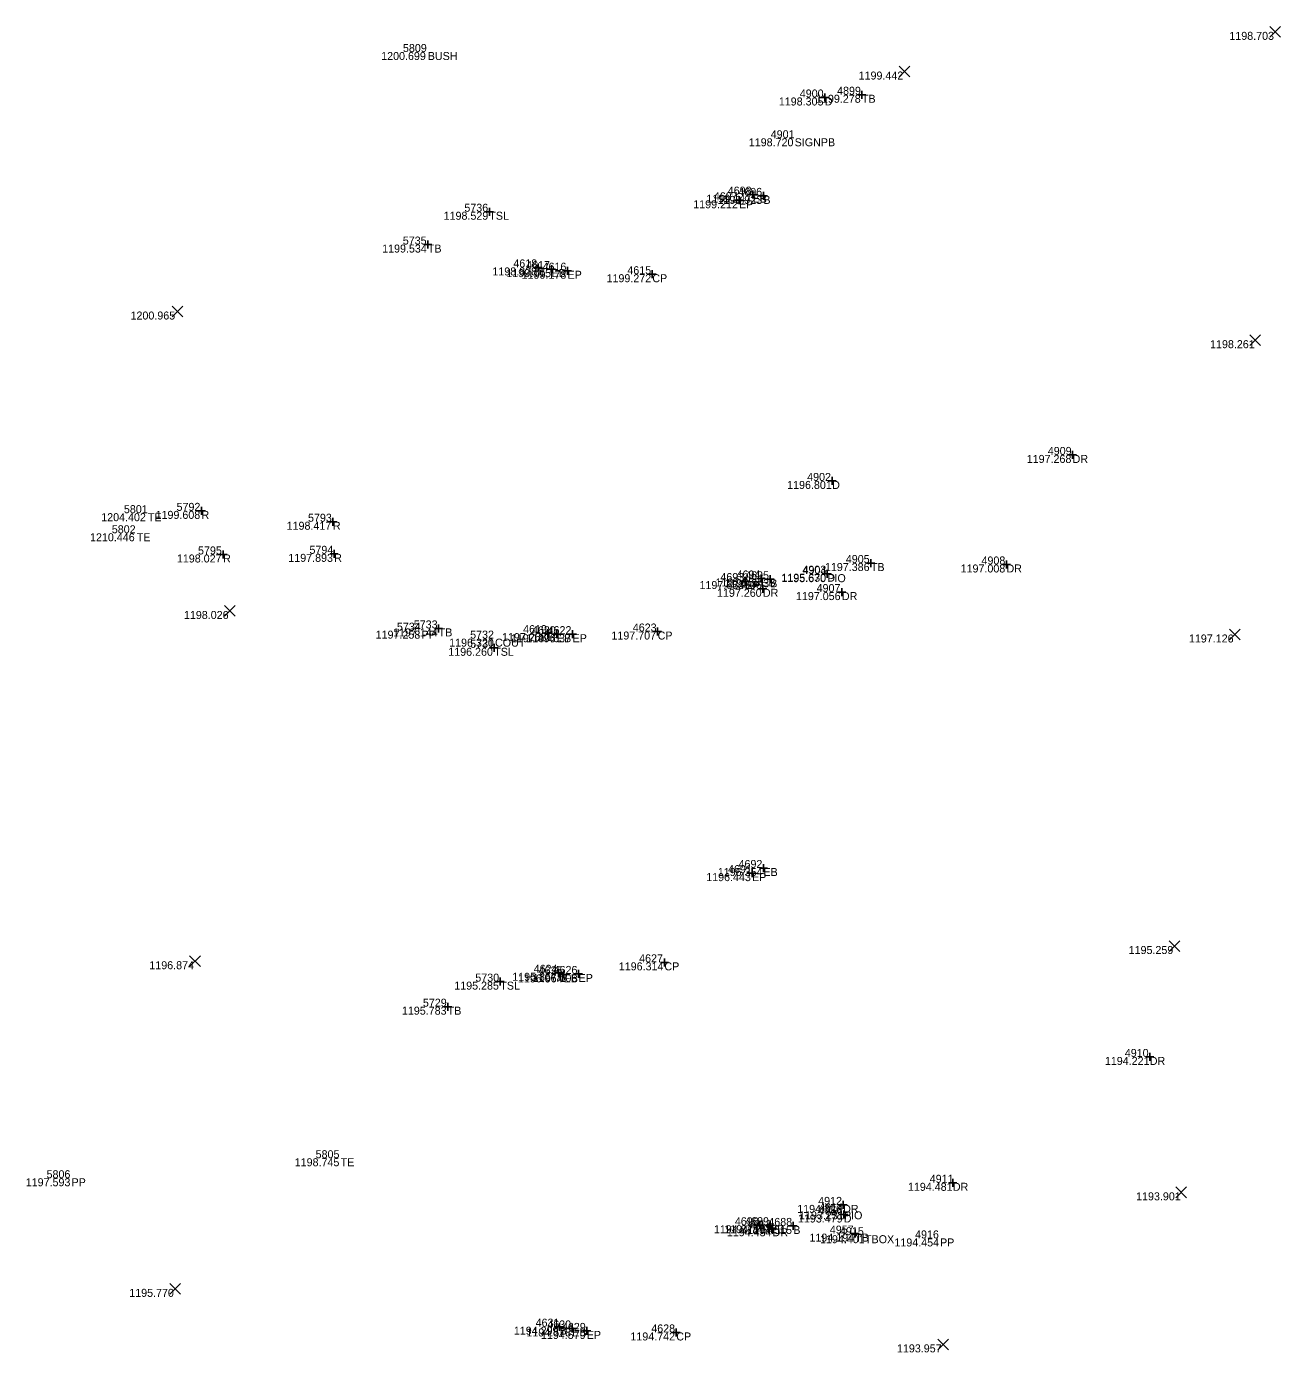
# Model space of a CAD drawing. Extents: x 2044997 to 2050342, y 455233 to 458054.
# Drawn here: x 2047566.8 to 2047723.4, y 456309.9 to 456475.6 of the extents above; entities that cross this region are included whole.
import ezdxf

# ---------------------------------------------------------------- set-up
doc = ezdxf.new("R2010")
doc.units = 0
for name, color, linetype in [('SV_X_Random_Point', 7, 'Continuous'), ('SV_X_Shot_Marker', 7, 'Continuous'), ('SV_X_Text_Comment', 7, 'Continuous'), ('SV_X_Text_Elevation', 7, 'Continuous'), ('SV_X_Text_Name', 7, 'Continuous')]:
    doc.layers.add(name, color=color, linetype=linetype)

msp = doc.modelspace()

# ---------------------------------------------------------------- linework, layer by layer
at = {"layer": 'SV_X_Random_Point'}
for p, q in [((2047722.08, 456474.27), (2047723.42, 456475.61)), ((2047722.08, 456475.61), (2047723.42, 456474.27)), ((2047675.78, 456469.31), (2047677.11, 456470.64)), ((2047675.78, 456470.64), (2047677.11, 456469.31)), ((2047584.95, 456439.32), (2047586.29, 456440.66)), ((2047584.95, 456440.66), (2047586.29, 456439.32)), ((2047719.57, 456435.74), (2047720.9, 456437.07)), ((2047719.57, 456437.07), (2047720.9, 456435.74)), ((2047591.51, 456401.9), (2047592.84, 456403.24)), ((2047591.51, 456403.24), (2047592.84, 456401.9)), ((2047717.05, 456398.97), (2047718.39, 456400.3)), ((2047717.05, 456400.3), (2047718.39, 456398.97)), ((2047709.5, 456360.03), (2047710.83, 456361.36)), ((2047709.5, 456361.36), (2047710.83, 456360.03)), ((2047587.15, 456358.13), (2047588.49, 456359.46)), ((2047587.15, 456359.46), (2047588.49, 456358.13)), ((2047710.33, 456329.25), (2047711.66, 456330.59)), ((2047710.33, 456330.59), (2047711.66, 456329.25)), ((2047584.67, 456317.19), (2047586.01, 456318.53)), ((2047584.67, 456318.53), (2047586.01, 456317.19)), ((2047680.62, 456310.25), (2047681.95, 456311.59)), ((2047680.62, 456311.59), (2047681.95, 456310.25))]:
    msp.add_line(p, q, dxfattribs=at)
at = {"layer": 'SV_X_Shot_Marker'}
for p, q in [((2047665.99, 456466.74), (2047666.99, 456466.74)), ((2047666.49, 456467.24), (2047666.49, 456466.24)), ((2047666.49, 456466.74), (2047666.49, 456466.74)), ((2047670.63, 456467.08), (2047671.63, 456467.08)), ((2047671.13, 456467.58), (2047671.13, 456466.58)), ((2047671.13, 456467.08), (2047671.13, 456467.08)), ((2047657.49, 456455.1), (2047657.49, 456454.1)), ((2047658.82, 456454.94), (2047658.82, 456453.94)), ((2047655.29, 456453.89), (2047656.29, 456453.89)), ((2047655.79, 456454.39), (2047655.79, 456453.39)), ((2047655.79, 456453.89), (2047655.79, 456453.89)), ((2047656.99, 456454.6), (2047657.99, 456454.6)), ((2047657.49, 456454.6), (2047657.49, 456454.6)), ((2047658.32, 456454.44), (2047659.32, 456454.44)), ((2047658.82, 456454.44), (2047658.82, 456454.44)), ((2047624.09, 456452.46), (2047625.09, 456452.46)), ((2047624.59, 456452.96), (2047624.59, 456451.96)), ((2047624.59, 456452.46), (2047624.59, 456452.46)), ((2047616.41, 456448.36), (2047617.41, 456448.36)), ((2047616.91, 456448.86), (2047616.91, 456447.86)), ((2047616.91, 456448.36), (2047616.91, 456448.36)), ((2047630.21, 456445.5), (2047631.21, 456445.5)), ((2047630.71, 456446), (2047630.71, 456445)), ((2047630.71, 456445.5), (2047630.71, 456445.5)), ((2047631.86, 456445.29), (2047632.86, 456445.29)), ((2047632.36, 456445.79), (2047632.36, 456444.79)), ((2047632.36, 456445.29), (2047632.36, 456445.29)), ((2047633.86, 456445.09), (2047634.86, 456445.09)), ((2047634.36, 456445.59), (2047634.36, 456444.59)), ((2047634.36, 456445.09), (2047634.36, 456445.09)), ((2047644.95, 456445.15), (2047644.95, 456444.15)), ((2047644.45, 456444.65), (2047645.45, 456444.65)), ((2047644.95, 456444.65), (2047644.95, 456444.65)), ((2047696.95, 456422.07), (2047697.95, 456422.07)), ((2047697.45, 456422.57), (2047697.45, 456421.57)), ((2047697.45, 456422.07), (2047697.45, 456422.07)), ((2047666.91, 456418.82), (2047667.91, 456418.82)), ((2047667.41, 456419.32), (2047667.41, 456418.32)), ((2047667.41, 456418.82), (2047667.41, 456418.82)), ((2047588.13, 456415.08), (2047589.13, 456415.08)), ((2047588.63, 456415.58), (2047588.63, 456414.58)), ((2047588.63, 456415.08), (2047588.63, 456415.08)), ((2047604.55, 456413.72), (2047605.55, 456413.72)), ((2047605.05, 456414.22), (2047605.05, 456413.22)), ((2047605.05, 456413.72), (2047605.05, 456413.72)), ((2047591.33, 456410.13), (2047591.33, 456409.13)), ((2047605.21, 456410.21), (2047605.21, 456409.21)), ((2047590.83, 456409.63), (2047591.83, 456409.63)), ((2047591.33, 456409.63), (2047591.33, 456409.63)), ((2047604.71, 456409.71), (2047605.71, 456409.71)), ((2047605.21, 456409.71), (2047605.21, 456409.71)), ((2047671.75, 456408.56), (2047672.75, 456408.56)), ((2047672.25, 456409.06), (2047672.25, 456408.06)), ((2047672.25, 456408.56), (2047672.25, 456408.56)), ((2047688.69, 456408.38), (2047689.69, 456408.38)), ((2047689.19, 456408.88), (2047689.19, 456407.88)), ((2047689.19, 456408.38), (2047689.19, 456408.38)), ((2047656.56, 456406.81), (2047656.56, 456405.81)), ((2047658.56, 456407.13), (2047658.56, 456406.13)), ((2047659.68, 456407.03), (2047659.68, 456406.03)), ((2047666.31, 456407.23), (2047667.31, 456407.23)), ((2047666.81, 456407.73), (2047666.81, 456406.73)), ((2047666.81, 456407.23), (2047666.81, 456407.23)), ((2047656.06, 456406.31), (2047657.06, 456406.31)), ((2047656.56, 456406.31), (2047656.56, 456406.31)), ((2047658.06, 456406.63), (2047659.06, 456406.63)), ((2047658.26, 456405.34), (2047659.26, 456405.34)), ((2047658.56, 456406.63), (2047658.56, 456406.63)), ((2047658.76, 456405.84), (2047658.76, 456404.84)), ((2047658.76, 456405.34), (2047658.76, 456405.34)), ((2047659.18, 456406.53), (2047660.18, 456406.53)), ((2047659.68, 456406.53), (2047659.68, 456406.53)), ((2047668.63, 456405.43), (2047668.63, 456404.43)), ((2047668.13, 456404.93), (2047669.13, 456404.93)), ((2047668.63, 456404.93), (2047668.63, 456404.93)), ((2047617.76, 456400.39), (2047618.76, 456400.39)), ((2047618.26, 456400.89), (2047618.26, 456399.89)), ((2047618.26, 456400.39), (2047618.26, 456400.39)), ((2047631.91, 456400.3), (2047631.91, 456399.3)), ((2047633.03, 456400.16), (2047633.03, 456399.16)), ((2047634.99, 456400.17), (2047634.99, 456399.17)), ((2047645.61, 456400.5), (2047645.61, 456399.5)), ((2047625.2, 456398.47), (2047625.2, 456397.47)), ((2047631.41, 456399.8), (2047632.41, 456399.8)), ((2047631.91, 456399.8), (2047631.91, 456399.8)), ((2047632.53, 456399.66), (2047633.53, 456399.66)), ((2047633.03, 456399.66), (2047633.03, 456399.66)), ((2047634.49, 456399.67), (2047635.49, 456399.67)), ((2047634.99, 456399.67), (2047634.99, 456399.67)), ((2047645.11, 456400), (2047646.11, 456400)), ((2047645.61, 456400), (2047645.61, 456400)), ((2047624.7, 456397.97), (2047625.7, 456397.97)), ((2047625.2, 456397.97), (2047625.2, 456397.97)), ((2047657.41, 456370.31), (2047657.41, 456369.31)), ((2047658.33, 456370.45), (2047659.33, 456370.45)), ((2047658.83, 456370.95), (2047658.83, 456369.95)), ((2047658.83, 456370.45), (2047658.83, 456370.45)), ((2047656.91, 456369.81), (2047657.91, 456369.81)), ((2047657.41, 456369.81), (2047657.41, 456369.81)), ((2047645.96, 456358.66), (2047646.96, 456358.66)), ((2047646.46, 456359.16), (2047646.46, 456358.16)), ((2047646.46, 456358.66), (2047646.46, 456358.66)), ((2047632.72, 456357.35), (2047633.72, 456357.35)), ((2047633.22, 456357.85), (2047633.22, 456356.85)), ((2047633.22, 456357.35), (2047633.22, 456357.35)), ((2047633.37, 456357.15), (2047634.37, 456357.15)), ((2047633.87, 456357.65), (2047633.87, 456356.65)), ((2047633.87, 456357.15), (2047633.87, 456357.15)), ((2047635.24, 456357.21), (2047636.24, 456357.21)), ((2047635.74, 456357.71), (2047635.74, 456356.71)), ((2047635.74, 456357.21), (2047635.74, 456357.21)), ((2047625.46, 456356.25), (2047626.46, 456356.25)), ((2047625.96, 456356.75), (2047625.96, 456355.75)), ((2047625.96, 456356.25), (2047625.96, 456356.25)), ((2047619.39, 456353.62), (2047619.39, 456352.62)), ((2047618.89, 456353.12), (2047619.89, 456353.12)), ((2047619.39, 456353.12), (2047619.39, 456353.12)), ((2047707.09, 456347.34), (2047707.09, 456346.34)), ((2047706.59, 456346.84), (2047707.59, 456346.84)), ((2047707.09, 456346.84), (2047707.09, 456346.84)), ((2047681.99, 456331.11), (2047682.99, 456331.11)), ((2047682.49, 456331.61), (2047682.49, 456330.61)), ((2047682.49, 456331.11), (2047682.49, 456331.11)), ((2047668.78, 456328.85), (2047668.78, 456327.85)), ((2047668.28, 456328.35), (2047669.28, 456328.35)), ((2047668.36, 456327.15), (2047669.36, 456327.15)), ((2047668.78, 456328.35), (2047668.78, 456328.35)), ((2047668.86, 456327.65), (2047668.86, 456326.65)), ((2047668.86, 456327.15), (2047668.86, 456327.15)), ((2047657.88, 456325.8), (2047658.88, 456325.8)), ((2047658.38, 456326.3), (2047658.38, 456325.3)), ((2047658.38, 456325.8), (2047658.38, 456325.8)), ((2047659.15, 456325.81), (2047660.15, 456325.81)), ((2047659.65, 456326.31), (2047659.65, 456325.31)), ((2047659.65, 456325.81), (2047659.65, 456325.81)), ((2047659.97, 456325.93), (2047659.97, 456324.93)), ((2047662.06, 456325.72), (2047663.06, 456325.72)), ((2047662.56, 456326.22), (2047662.56, 456325.22)), ((2047662.56, 456325.72), (2047662.56, 456325.72)), ((2047659.47, 456325.43), (2047660.47, 456325.43)), ((2047659.97, 456325.43), (2047659.97, 456325.43)), ((2047669.79, 456324.76), (2047670.79, 456324.76)), ((2047670.29, 456325.26), (2047670.29, 456324.26)), ((2047670.29, 456324.76), (2047670.29, 456324.76)), ((2047632.87, 456313.13), (2047633.87, 456313.13)), ((2047633.37, 456313.63), (2047633.37, 456312.63)), ((2047633.37, 456313.13), (2047633.37, 456313.13)), ((2047634.45, 456312.91), (2047635.45, 456312.91)), ((2047634.95, 456313.41), (2047634.95, 456312.41)), ((2047634.95, 456312.91), (2047634.95, 456312.91)), ((2047636.26, 456312.6), (2047637.26, 456312.6)), ((2047636.76, 456313.1), (2047636.76, 456312.1)), ((2047636.76, 456312.6), (2047636.76, 456312.6)), ((2047647.44, 456312.41), (2047648.44, 456312.41)), ((2047647.94, 456312.91), (2047647.94, 456311.91)), ((2047647.94, 456312.41), (2047647.94, 456312.41))]:
    msp.add_line(p, q, dxfattribs=at)

# ---------------------------------------------------------------- texts
at = {"layer": 'SV_X_Text_Comment'}
for s, p in [('BUSH', (2047616.9, 456471.42)), ('D', (2047666.49, 456465.74)), ('TB', (2047671.13, 456466.08)), ('SIGNPB', (2047662.73, 456460.64)), ('EP', (2047655.79, 456452.89)), ('EB', (2047657.49, 456453.6)), ('B', (2047658.82, 456453.44)), ('TSL', (2047624.59, 456451.46)), ('TB', (2047616.91, 456447.36)), ('B', (2047630.71, 456444.5)), ('EB', (2047632.36, 456444.29)), ('EP', (2047634.36, 456444.09)), ('CP', (2047644.95, 456443.65)), ('DR', (2047697.45, 456421.07)), ('D', (2047667.41, 456417.82)), ('R', (2047588.63, 456414.08)), ('TE', (2047581.94, 456413.79)), ('R', (2047605.05, 456412.72)), ('TE', (2047580.55, 456411.28)), ('R', (2047591.33, 456408.63)), ('R', (2047605.21, 456408.71)), ('TB', (2047672.25, 456407.56)), ('DR', (2047689.19, 456407.38)), ('D', (2047666.81, 456406.23)), ('PIO', (2047666.81, 456406.17)), ('EP', (2047656.56, 456405.31)), ('EB', (2047658.56, 456405.63)), ('DR', (2047658.76, 456404.34)), ('B', (2047659.68, 456405.53)), ('DR', (2047668.63, 456403.93)), ('PP', (2047616.13, 456399.11)), ('TB', (2047618.26, 456399.39)), ('CP', (2047645.61, 456399)), ('COUT', (2047625.3, 456398.11)), ('B', (2047631.91, 456398.8)), ('EB', (2047633.03, 456398.66)), ('EP', (2047634.99, 456398.67)), ('TSL', (2047625.2, 456396.97)), ('EB', (2047658.83, 456369.45)), ('EP', (2047657.41, 456368.81)), ('CP', (2047646.46, 456357.66)), ('B', (2047633.22, 456356.35)), ('EB', (2047633.87, 456356.15)), ('EP', (2047635.74, 456356.21)), ('TSL', (2047625.96, 456355.25)), ('TB', (2047619.39, 456352.12)), ('DR', (2047707.09, 456345.84)), ('TE', (2047606.02, 456333.18)), ('PP', (2047572.4, 456330.68)), ('DR', (2047682.49, 456330.11)), ('DR', (2047668.78, 456327.35)), ('D', (2047668.86, 456326.15)), ('PIO', (2047668.89, 456326.55)), ('EP', (2047658.38, 456324.8)), ('EB', (2047659.65, 456324.81)), ('B', (2047662.56, 456324.72)), ('DR', (2047659.97, 456324.43)), ('TB', (2047670.29, 456323.76)), ('TBOX', (2047671.52, 456323.56)), ('PP', (2047680.89, 456323.16)), ('B', (2047633.37, 456312.13)), ('EB', (2047634.95, 456311.91)), ('EP', (2047636.76, 456311.6)), ('CP', (2047647.94, 456311.41))]:
    msp.add_text(s, height=1, dxfattribs=at).set_placement(p)
at = {"layer": 'SV_X_Text_Elevation'}
for s, p in [('1198.703', (2047717.03, 456473.94)), ('1200.699', (2047611.08, 456471.42)), ('1199.442', (2047670.72, 456468.98)), ('1198.305', (2047660.75, 456465.74)), ('1199.278', (2047665.4, 456466.08)), ('1198.720', (2047657, 456460.64)), ('1199.212', (2047650.06, 456452.89)), ('1199.147', (2047651.71, 456453.6)), ('1198.923', (2047653.09, 456453.44)), ('1198.529', (2047618.88, 456451.46)), ('1199.534', (2047611.2, 456447.36)), ('1198.828', (2047624.97, 456444.5)), ('1199.115', (2047626.72, 456444.29)), ('1199.178', (2047628.63, 456444.09)), ('1199.272', (2047639.23, 456443.65)), ('1200.965', (2047579.77, 456438.99)), ('1198.261', (2047714.62, 456435.41)), ('1197.268', (2047691.72, 456421.07)), ('1196.801', (2047661.79, 456417.82)), ('1199.608', (2047582.9, 456414.08)), ('1204.402', (2047576.11, 456413.79)), ('1198.417', (2047599.27, 456412.72)), ('1210.446', (2047574.71, 456411.28)), ('1198.027', (2047585.56, 456408.63)), ('1197.893', (2047599.48, 456408.71)), ('1197.386', (2047666.51, 456407.56)), ('1197.008', (2047683.46, 456407.38)), ('1197.553', (2047652.84, 456405.63)), ('1195.630', (2047661.08, 456406.23)), ('1195.670', (2047661.07, 456406.17)), ('1197.653', (2047650.84, 456405.31)), ('1197.260', (2047653.03, 456404.34)), ('1197.343', (2047653.96, 456405.53)), ('1197.056', (2047662.89, 456403.93)), ('1198.026', (2047586.44, 456401.57)), ('1197.258', (2047610.39, 456399.11)), ('1197.144', (2047612.56, 456399.39)), ('1197.707', (2047639.84, 456399)), ('1196.320', (2047619.57, 456398.11)), ('1197.268', (2047626.17, 456398.8)), ('1197.496', (2047627.29, 456398.66)), ('1197.637', (2047629.21, 456398.67)), ('1197.126', (2047711.98, 456398.63)), ('1196.260', (2047619.46, 456396.97)), ('1196.354', (2047653.13, 456369.45)), ('1196.443', (2047651.68, 456368.81)), ('1195.259', (2047704.45, 456359.7)), ('1196.874', (2047582.12, 456357.8)), ('1196.314', (2047640.76, 456357.66)), ('1195.867', (2047627.45, 456356.35)), ('1196.064', (2047628.16, 456356.15)), ('1196.106', (2047630, 456356.21)), ('1195.285', (2047620.21, 456355.25)), ('1195.783', (2047613.67, 456352.12)), ('1194.221', (2047701.48, 456345.84)), ('1198.745', (2047600.28, 456333.18)), ('1197.593', (2047566.68, 456330.68)), ('1194.481', (2047676.88, 456330.11)), ('1193.901', (2047705.38, 456328.92)), ('1194.326', (2047663.05, 456327.35)), ('1193.479', (2047663.14, 456326.15)), ('1193.231', (2047663.28, 456326.55)), ('1194.878', (2047652.64, 456324.8)), ('1194.749', (2047653.94, 456324.81)), ('1194.515', (2047656.82, 456324.72)), ('1194.434', (2047654.26, 456324.43)), ('1194.194', (2047664.58, 456323.76)), ('1194.401', (2047665.9, 456323.56)), ('1194.454', (2047675.19, 456323.16)), ('1195.770', (2047579.61, 456316.86)), ('1194.299', (2047627.65, 456312.13)), ('1194.578', (2047629.22, 456311.91)), ('1194.579', (2047631.04, 456311.6)), ('1194.742', (2047642.21, 456311.41)), ('1193.957', (2047675.51, 456309.92))]:
    msp.add_text(s, height=1, dxfattribs=at).set_placement(p)
at = {"layer": 'SV_X_Text_Name'}
for s, p in [('5809', (2047613.8, 456472.42)), ('4899', (2047668.03, 456467.08)), ('4900', (2047663.37, 456466.74)), ('4901', (2047659.74, 456461.64)), ('4697', (2047652.63, 456453.89)), ('4698', (2047654.37, 456454.6)), ('4696', (2047655.69, 456454.44)), ('5736', (2047621.47, 456452.46)), ('5735', (2047613.78, 456448.36)), ('4618', (2047627.59, 456445.5)), ('4617', (2047629.19, 456445.29)), ('4616', (2047631.24, 456445.09)), ('4615', (2047641.83, 456444.65)), ('4909', (2047694.35, 456422.07)), ('4902', (2047664.29, 456418.82)), ('5801', (2047578.94, 456414.79)), ('5792', (2047585.52, 456415.08)), ('5802', (2047577.43, 456412.28)), ('5793', (2047601.94, 456413.72)), ('5795', (2047588.2, 456409.63)), ('5794', (2047602.12, 456409.71)), ('4905', (2047669.12, 456408.56)), ('4908', (2047686.07, 456408.38)), ('4693', (2047653.45, 456406.31)), ('4694', (2047655.47, 456406.63)), ('4695', (2047656.55, 456406.53)), ('4903', (2047663.7, 456407.23)), ('4904', (2047663.72, 456407.17)), ('4906', (2047655.64, 456405.34)), ('4907', (2047665.47, 456404.93)), ('5734', (2047613.04, 456400.11)), ('5733', (2047615.15, 456400.39)), ('5732', (2047622.19, 456399.11)), ('4619', (2047628.81, 456399.8)), ('4620', (2047629.91, 456399.66)), ('4622', (2047631.87, 456399.67)), ('4623', (2047642.51, 456400)), ('5731', (2047622.2, 456397.97)), ('4691', (2047654.41, 456369.81)), ('4692', (2047655.72, 456370.45)), ('4627', (2047643.3, 456358.66)), ('5730', (2047622.84, 456356.25)), ('4624', (2047630.13, 456357.35)), ('4625', (2047630.74, 456357.15)), ('4626', (2047632.62, 456357.21)), ('5729', (2047616.29, 456353.12)), ('4910', (2047703.97, 456346.84)), ('5805', (2047602.89, 456334.18)), ('5806', (2047569.28, 456331.68)), ('4911', (2047679.6, 456331.11)), ('4912', (2047665.67, 456328.35)), ('4956', (2047665.74, 456327.15)), ('4914', (2047665.8, 456327.55)), ('4690', (2047655.26, 456325.8)), ('4689', (2047656.55, 456325.81)), ('4913', (2047656.86, 456325.43)), ('4688', (2047659.44, 456325.72)), ('4957', (2047667.12, 456324.76)), ('4915', (2047668.39, 456324.56)), ('4916', (2047677.77, 456324.16)), ('4631', (2047630.37, 456313.13)), ('4630', (2047631.83, 456312.91)), ('4629', (2047633.66, 456312.6)), ('4628', (2047644.82, 456312.41))]:
    msp.add_text(s, height=1, dxfattribs=at).set_placement(p)

doc.saveas('drawing.dxf')
